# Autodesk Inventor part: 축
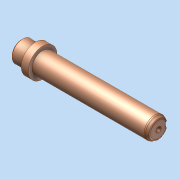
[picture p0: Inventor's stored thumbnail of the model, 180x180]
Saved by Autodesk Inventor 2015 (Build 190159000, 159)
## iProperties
Created: 2026-02
Part Number: 축
Material: 일반
Document SubType Name: Modeling
Designer: Administrator
Density: 1 g/cm^3
Appearance: 기본값
Author: Administrator
Author: jhkim
Creation Date: 2026-01-30
Sending System: Autodesk Inventor 2026
Preprocessor: ST-DEVELOPER v20.1
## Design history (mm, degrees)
node "축1"
node "솔리드1"
node "기준1"
